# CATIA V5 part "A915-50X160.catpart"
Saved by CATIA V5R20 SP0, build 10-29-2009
Part number: A915-50X160
Source: Unknown
Property "A": "0.000"
Property "ARTICLENO": "A915-50X160"
Property "BOMINFO": "A915-50X160"
Property "CODE": "A915-50X160"
Property "CREATOR": "CADENAS GmbH"
Property "D": "13.500"
Property "D1": "20.000"
Property "FORM": "B"
Property "L": "160.000"
Property "L1": "25.000"
Property "L2": "110.000"
Property "LINA": "A915-50X160"
Property "NB": "A915-50X160"
Property "NBSYN": "$CODE."
Property "NN": "A915"
Property "NT": "VDI 3357 Wear Plates, steel"
Property "SCREW": "M12x25"
Property "SUPPLIER": "CF"
Property "T": "13.000"
Property "W": "50.000"
Bounding box of the stored display mesh (mm): x 0 to 20, y 0 to 160, z -25 to 25
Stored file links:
  C:\Users\borellobunino\Desktop\3D X SITO CF\A915\GSB_OILLESS_G22501050160\A915-50X160.catpart
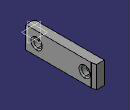
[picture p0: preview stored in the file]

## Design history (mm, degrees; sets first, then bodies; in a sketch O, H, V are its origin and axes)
Body1 "Geometry.1" (main body)
  Solid1 "A915-50X160.catpart": solid without history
